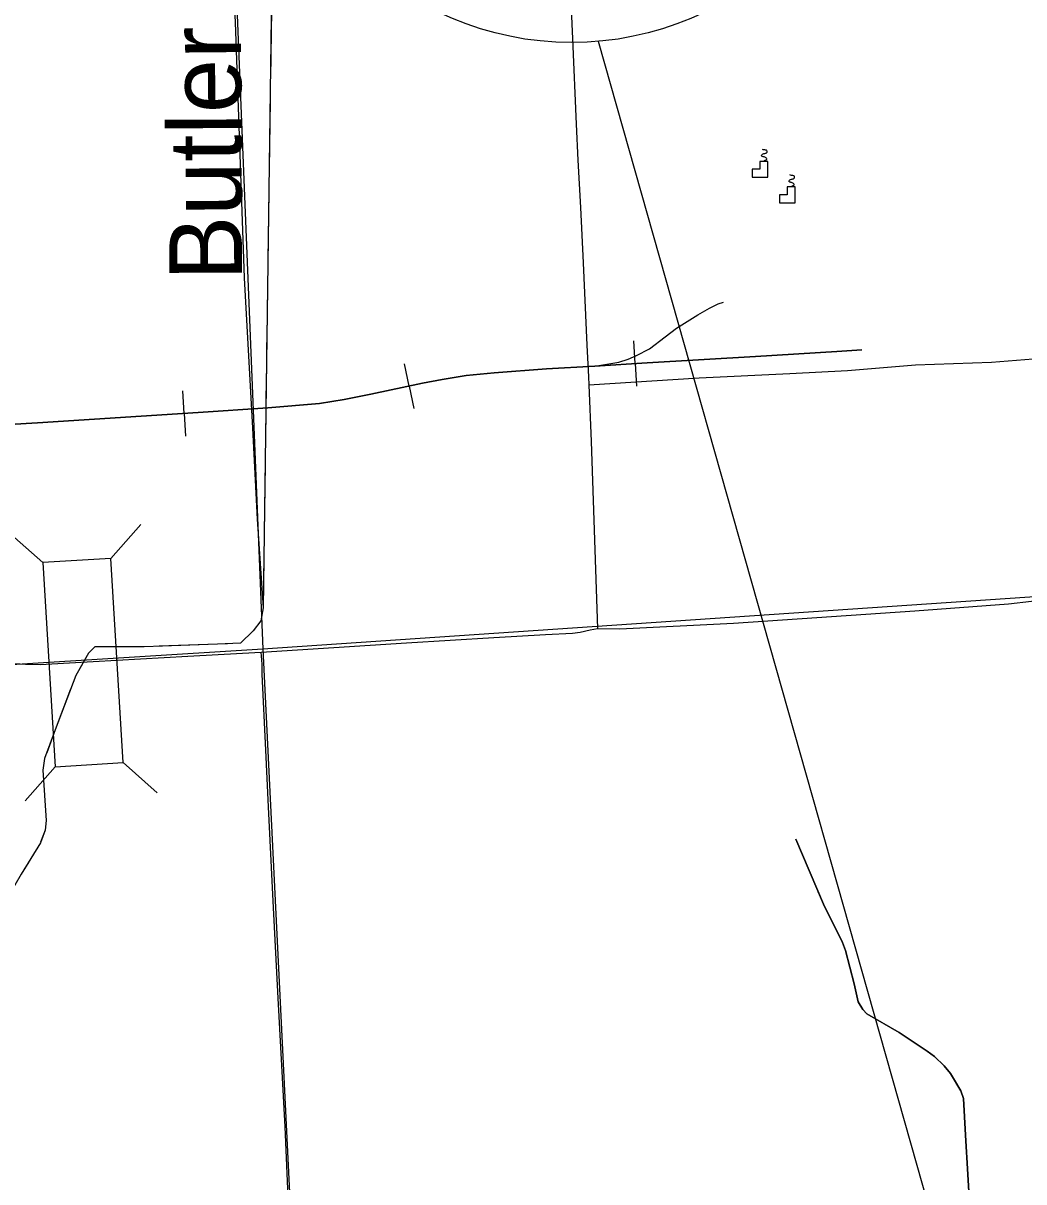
# Model space of a CAD drawing. Extents: x 646058 to 725608, y 1473014 to 1561048.
# Drawn here: x 662655 to 665563, y 1549300 to 1552665 of the extents above; entities that cross this region are included whole.
import ezdxf

# ---------------------------------------------------------------- set-up
doc = ezdxf.new("R2010")
doc.units = 0
doc.layers.add('Default', color=7, linetype='Continuous')
doc.layers.add('R_Grid', color=7, linetype='Continuous')

msp = doc.modelspace()

# ---------------------------------------------------------------- linework, layer by layer
at = {"layer": 'Default'}
for p, q in [((664433, 1551676.4), (664429.1, 1551742.2)), ((663777.2, 1551611), (663763.5, 1551675.6)), ((664433, 1551676.4), (664437, 1551610.5)), ((663777.2, 1551611), (663790.8, 1551546.4)), ((663123.1, 1551531.7), (663118.9, 1551597.6)), ((663123.1, 1551531.7), (663127.3, 1551465.9)), ((662909.7, 1551110.6), (662997.2, 1551209.4)), ((662712.1, 1551098.6), (662613.3, 1551186.1)), ((662748.2, 1550505.7), (662660.7, 1550406.8)), ((662945.8, 1550517.7), (663044.6, 1550430.2))]:
    msp.add_line(p, q, dxfattribs=at)
for points in [[(663226.3, 1553567.9), (663232.5, 1553395.6), (663270.9, 1552668.3), (663297.1, 1551925.6), (663321.7, 1551488.8), (663335.5, 1551224.3), (663352.4, 1550967.5), (663346.3, 1550929.1), (663323.2, 1550899.9), (663286.3, 1550864.5), (663220.2, 1550861.4), (663006.5, 1550853.7), (662863.5, 1550853.7), (662845.1, 1550835.3), (662808.2, 1550770.7), (662748.2, 1550612.3), (662717.5, 1550529.3), (662712.8, 1550495.4), (662722.1, 1550349.4), (662719, 1550321.7), (662705.2, 1550284.8), (662649.8, 1550194)], [(664210.5, 1553537.4), (664227.5, 1553214.6), (664227.8, 1553168.1), (664230, 1553107.5), (664240.1, 1552883.1), (664251.7, 1552619.1), (664262.3, 1552371.4), (664266.9, 1552266.8), (664274.6, 1552129.5), (664282.6, 1551968.6), (664293, 1551729.9), (664297.5, 1551638.3), (664298.5, 1551614.7)], [(663245.3, 1553479.5), (663352, 1550847.2)], [(664213.7, 1553477.8), (664227.5, 1553214.6), (664227.8, 1553168.1), (664230, 1553107.5), (664240.1, 1552883.1), (664251.7, 1552619.1), (664262.3, 1552371.4), (664266.9, 1552266.8), (664274.6, 1552129.5), (664282.6, 1551968.6), (664293, 1551729.9), (664297.5, 1551638.3), (664298.5, 1551614.7)], [(663386, 1553396.4), (663352.4, 1550967.5)], [(663376.4, 1552703.5), (663373.7, 1552505.5)], [(663372.7, 1552439.5), (663370, 1552241.6)], [(664807.9, 1552264.3), (664808, 1552264.6), (664808.1, 1552265), (664808.5, 1552265.4), (664808.8, 1552265.7), (664809, 1552265.9), (664809.3, 1552266.2), (664809.6, 1552266.4), (664809.9, 1552266.6), (664810.6, 1552267), (664811.1, 1552267.2), (664811.7, 1552267.4), (664812.6, 1552267.6), (664813.5, 1552267.9), (664814.5, 1552268.5), (664815.2, 1552269.2), (664815.6, 1552270.2), (664815.6, 1552271.3), (664815.2, 1552272.3), (664814.2, 1552273.6), (664812.2, 1552274.9), (664810.3, 1552275.8), (664807.9, 1552276.6), (664806.2, 1552276.9), (664805, 1552277.1), (664803.7, 1552277.4), (664801.9, 1552278.2), (664800.9, 1552279.4), (664800.6, 1552280.9), (664801, 1552282.4), (664801.9, 1552283.6), (664803.3, 1552284.7), (664805, 1552285.5), (664807.7, 1552286.2), (664810.1, 1552286.8), (664812.2, 1552287.2), (664813.7, 1552287.6), (664815.2, 1552288.6), (664816.5, 1552290.3), (664816.9, 1552291.9), (664816.8, 1552293.4), (664816.4, 1552294.6), (664814.5, 1552295.9), (664811.8, 1552296.6), (664810, 1552296.7), (664808.2, 1552296.9), (664805.5, 1552297.6), (664803.4, 1552298.5)], [(664887.4, 1552190), (664887.6, 1552190.3), (664887.7, 1552190.6), (664888.1, 1552191), (664888.3, 1552191.4), (664888.5, 1552191.6), (664888.9, 1552191.9), (664889.1, 1552192.1), (664889.5, 1552192.3), (664890.2, 1552192.6), (664890.7, 1552192.8), (664891.3, 1552193), (664892.1, 1552193.2), (664893, 1552193.6), (664894, 1552194.1), (664894.7, 1552194.9), (664895.1, 1552195.8), (664895.2, 1552196.9), (664894.7, 1552198), (664893.8, 1552199.3), (664891.8, 1552200.6), (664889.9, 1552201.5), (664887.5, 1552202.2), (664885.8, 1552202.6), (664884.6, 1552202.8), (664883.2, 1552203), (664881.5, 1552203.9), (664880.4, 1552205.1), (664880.1, 1552206.6), (664880.6, 1552208), (664881.5, 1552209.2), (664882.9, 1552210.4), (664884.6, 1552211.1), (664887.3, 1552211.9), (664889.6, 1552212.4), (664891.8, 1552212.8), (664893.3, 1552213.3), (664894.8, 1552214.3), (664896.1, 1552215.9), (664896.4, 1552217.5), (664896.4, 1552219), (664896, 1552220.2), (664894, 1552221.6), (664891.3, 1552222.2), (664889.6, 1552222.3), (664887.8, 1552222.5), (664885.1, 1552223.3), (664883, 1552224.2)], [(663369.1, 1552175.6), (663366.4, 1551977.6)], [(663365.5, 1551911.6), (663364.1, 1551812.6)], [(664315.8, 1551669.3), (664385.7, 1551680.9), (664412.8, 1551689), (664437.3, 1551699.7), (664475.1, 1551719.3), (664520.4, 1551753.9), (664553.7, 1551779), (664615.4, 1551818.1), (664649.4, 1551836.9), (664674.5, 1551849.5), (664690.3, 1551855.2)], [(663364.1, 1551812.6), (663362.7, 1551713.6)], [(661571.7, 1551429), (661919.3, 1551452.5), (662157.5, 1551468.8), (662452, 1551489.3), (662697.3, 1551504.6), (663163.6, 1551534.3), (663366, 1551547.6), (663516.3, 1551560.9), (663587.9, 1551572.1), (663665.6, 1551587.5), (663815.9, 1551619.2), (663873.1, 1551630.4), (663942.6, 1551641.7), (664023.4, 1551649.9), (664175.7, 1551661.1), (664315.8, 1551669.3), (664468.1, 1551678.5), (664783, 1551696.9), (665019.2, 1551711.2), (665091.8, 1551716.3)], [(665091.8, 1551716.3), (665019.2, 1551711.2), (664783, 1551696.9), (664468.1, 1551678.5), (664315.8, 1551669.3), (664175.7, 1551661.1), (664023.4, 1551649.9), (663942.6, 1551641.7), (663873.1, 1551630.4), (663815.9, 1551619.2), (663665.6, 1551587.5), (663587.9, 1551572.1), (663516.3, 1551560.9), (663366, 1551547.6), (663163.6, 1551534.3), (662697.3, 1551504.6), (662452, 1551489.3), (662157.5, 1551468.8), (661919.3, 1551452.5), (661571.7, 1551429)], [(665091.8, 1551716.3), (665019.2, 1551711.2), (664783, 1551696.9), (664468.1, 1551678.5), (664315.8, 1551669.3), (664175.7, 1551661.1), (664023.4, 1551649.9), (663942.6, 1551641.7), (663873.1, 1551630.4), (663815.9, 1551619.2), (663665.6, 1551587.5), (663587.9, 1551572.1), (663516.3, 1551560.9), (663366, 1551547.6), (663163.6, 1551534.3), (662697.3, 1551504.6), (662452, 1551489.3), (662157.5, 1551468.8), (661919.3, 1551452.5), (661571.7, 1551429)], [(664298.5, 1551614.7), (664619, 1551634.8), (664882.7, 1551647.8), (665050.4, 1551656.7), (665247.9, 1551672.8), (665468.3, 1551680.1), (665662.2, 1551695.6), (665940.9, 1551710.5)], [(664298.5, 1551614.7), (664619, 1551634.8), (664882.7, 1551647.8), (665050.4, 1551656.7), (665247.9, 1551672.8), (665468.3, 1551680.1), (665662.2, 1551695.6), (665924.6, 1551709.6)], [(663361.8, 1551647.6), (663359.1, 1551449.6)], [(664298.5, 1551614.7), (664305.9, 1551450), (664324.1, 1550906.6)], [(664298.5, 1551614.7), (664305.9, 1551450), (664324.1, 1550906.6)], [(663358.2, 1551383.6), (663355.4, 1551185.7)], [(663354.5, 1551119.7), (663352.4, 1550967.5)], [(664324.1, 1550906.6), (664388.9, 1550906.2), (664719.4, 1550922.6), (665245.8, 1550958.5), (665518.5, 1550978.6), (665651.5, 1550994.4), (665816.2, 1551010.5), (665957.9, 1551025.1), (666119.9, 1551039.9)], [(665965.9, 1551024.1), (663352, 1550847.2)], [(664324.1, 1550906.6), (664388.9, 1550906.2), (664719.4, 1550922.6), (665245.8, 1550958.5), (665518.5, 1550978.6), (665651.5, 1550994.4), (665816.2, 1551010.5), (665965.9, 1551026)], [(663352.4, 1550967.5), (663346.3, 1550929.1), (663323.2, 1550899.9), (663286.3, 1550864.5), (663220.2, 1550861.4), (663006.5, 1550853.7), (662863.5, 1550853.7), (662845.1, 1550835.3), (662808.2, 1550770.7), (662748.2, 1550612.3), (662717.5, 1550529.3), (662712.8, 1550495.4), (662722.1, 1550349.4), (662719, 1550321.7), (662705.2, 1550284.8), (662649.8, 1550194)], [(663352.4, 1550967.5), (663346.3, 1550929.1), (663323.2, 1550899.9), (663306.7, 1550884.1)], [(663347.2, 1550838.1), (663769.4, 1550865.5), (664023.2, 1550881), (664172.6, 1550889.5), (664251.6, 1550893.7), (664274, 1550896.8), (664302.2, 1550903), (664324.1, 1550906.6)], [(663347.2, 1550838.1), (663769.4, 1550865.5), (664023.2, 1550881), (664172.6, 1550889.5), (664251.6, 1550893.7), (664274, 1550896.8), (664302.2, 1550903), (664324.1, 1550906.6)], [(663248.6, 1550862.8), (663220.2, 1550861.4), (663050.7, 1550855.3)], [(663352, 1550847.2), (660709.3, 1550682.8)], [(662063.5, 1550780.2), (662363.2, 1550801.5), (662491, 1550809.2), (662545.2, 1550810.2), (662600.4, 1550807.3), (662662.4, 1550803.4), (662705, 1550802.5), (662790.2, 1550807.3), (663134, 1550826.7), (663292.8, 1550835.4), (663347.2, 1550838.1)], [(662063.5, 1550780.2), (662363.2, 1550801.5), (662491, 1550809.2), (662545.2, 1550810.2), (662600.4, 1550807.3), (662662.4, 1550803.4), (662705, 1550802.5), (662790.2, 1550807.3), (663134, 1550826.7), (663292.8, 1550835.4), (663347.2, 1550838.1)], [(662984.8, 1550853.7), (662863.5, 1550853.7), (662845.1, 1550835.3), (662819.9, 1550791.3)], [(663428.8, 1549166), (663416.3, 1549459.9), (663396.3, 1549833.8), (663381.4, 1550115.3), (663368, 1550389.3), (663360.5, 1550554.1), (663349.7, 1550774), (663349.7, 1550803.9), (663347.2, 1550838.1)], [(663428.8, 1549166), (663416.3, 1549459.9), (663396.3, 1549833.8), (663381.4, 1550115.3), (663368, 1550389.3), (663360.5, 1550554.1), (663349.7, 1550774), (663349.7, 1550803.9), (663347.2, 1550838.1)], [(663352, 1550847.2), (663480.2, 1548223.1)], [(662793.2, 1550731.2), (662748.2, 1550612.3), (662723.6, 1550545.8)], [(662713.7, 1550481.3), (662722.1, 1550349.4), (662719, 1550321.7), (662705.7, 1550286.1)], [(665406.9, 1549207.2), (665393.6, 1549435.8), (665387, 1549542.1), (665379.4, 1549564.8), (665350, 1549615.1), (665331, 1549636.9), (665302.6, 1549664.4), (665281.7, 1549679.6), (665200.2, 1549733.7), (665106.3, 1549787.8), (665094.9, 1549801), (665081.6, 1549822.9), (665069.3, 1549875), (665044.6, 1549971.8), (665036.1, 1549995.5), (664980.1, 1550106.5), (664900.5, 1550295.2)], [(664900.5, 1550295.2), (664980.1, 1550106.5), (665036.1, 1549995.5), (665044.6, 1549971.8), (665069.3, 1549875), (665081.6, 1549822.9), (665094.9, 1549801), (665106.3, 1549787.8), (665200.2, 1549733.7), (665281.7, 1549679.6), (665302.6, 1549664.4), (665331, 1549636.9), (665350, 1549615.1), (665379.4, 1549564.8), (665387, 1549542.1), (665393.6, 1549435.8), (665406.9, 1549207.2)], [(664900.5, 1550295.2), (664939, 1550204)], [(662671.5, 1550229.7), (662649.8, 1550194), (662571.1, 1550059)], [(664964.6, 1550143.2), (664980.1, 1550106.5), (665036.1, 1549995.5), (665044.6, 1549971.8), (665046.8, 1549963.4)], [(665063.1, 1549899.5), (665069.3, 1549875), (665081.6, 1549822.9), (665094.9, 1549801), (665106.3, 1549787.8), (665172.3, 1549749.8)], [(665228.3, 1549715), (665281.7, 1549679.6), (665302.6, 1549664.4), (665331, 1549636.9), (665350, 1549615.1), (665370, 1549580.9)], [(665388.4, 1549518.7), (665393.6, 1549435.8), (665400.3, 1549321.1)]]:
    msp.add_lwpolyline(points, dxfattribs=at)
for points in [[(664773, 1552217.8), (664818.9, 1552217.8), (664818.9, 1552263.7), (664796, 1552263.7), (664796, 1552240.8), (664773, 1552240.8)], [(664852.6, 1552143.5), (664898.5, 1552143.5), (664898.5, 1552189.4), (664875.5, 1552189.4), (664875.5, 1552166.4), (664852.6, 1552166.4)], [(662712.1, 1551098.6), (662748.2, 1550505.7), (662945.8, 1550517.7), (662909.7, 1551110.6)]]:
    msp.add_lwpolyline(points, close=True, dxfattribs=at)
at = {"layer": 'R_Grid'}
msp.add_line((667134.7, 1542708.4), (664326.9, 1552612.1), dxfattribs=at)
msp.add_circle((664248.5, 1553498.1), 889.4, dxfattribs=at)

# ---------------------------------------------------------------- texts
at = {"layer": 'Default'}
msp.add_text('Butler', height=211.2, rotation=90.2936, dxfattribs=at).set_placement((663291.6, 1551917.7))

doc.saveas('drawing.dxf')
